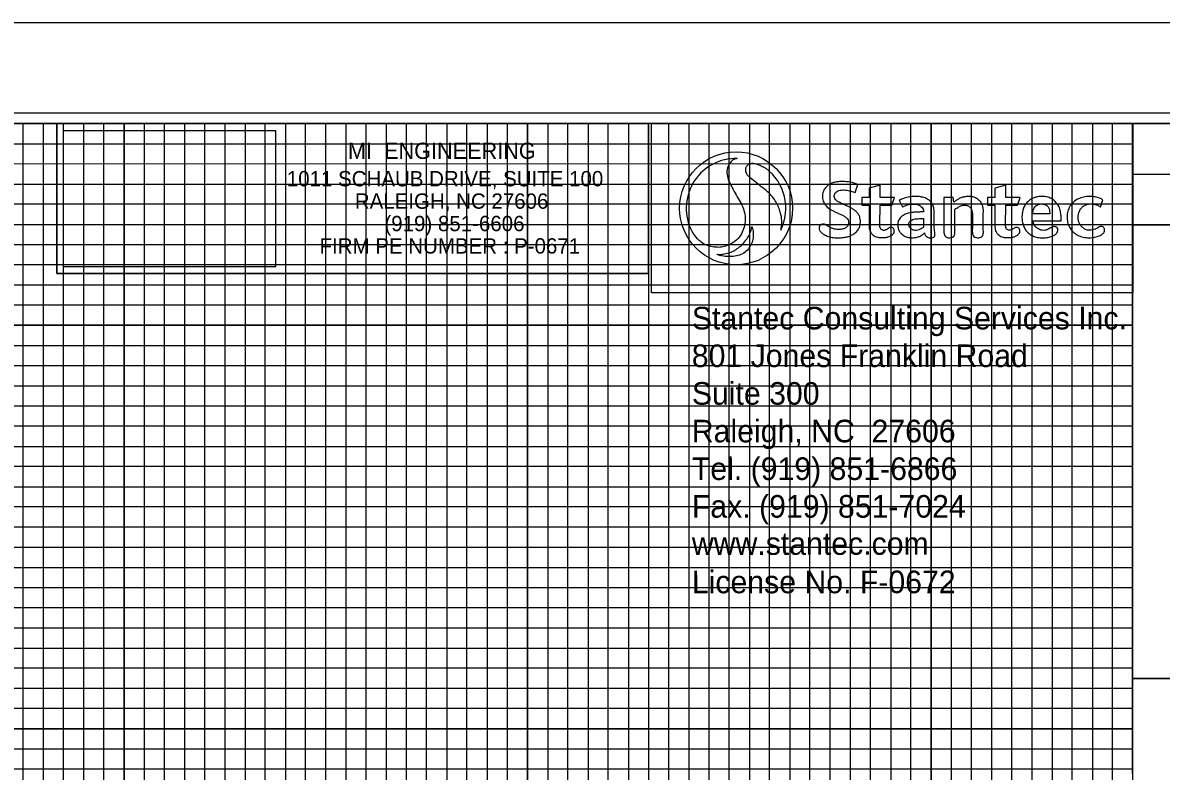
# Model space of a CAD drawing. Extents: x 2331575 to 2333259, y 609001 to 610101.
# Drawn here: x 2332767.1 to 2333049.3, y 609916 to 610101.5 of the extents above; entities that cross this region are included whole.
import ezdxf

# ---------------------------------------------------------------- set-up
doc = ezdxf.new("R2010")
doc.units = 0
for name, color, linetype in [('Old_Level_1', 7, 'Continuous'), ('Prop DSN Text', 7, 'Continuous'), ('Prop Grid Mask', 7, 'Continuous'), ('Scratch_Level_0', 7, 'Continuous'), ('Sheet Cutting Line CELL', 7, 'Continuous'), ('Sheet Data Text CELL', 7, 'Continuous'), ('Sheet DOT Grid CELL', 7, 'Continuous'), ('Sheet Plot Border Inside CELL', 7, 'Continuous'), ('Sheet Plot Border Outside CELL', 7, 'Continuous'), ('Sheet Profile CELL', 7, 'Continuous'), ('Sheet Profile Grid Major CELL', 7, 'Continuous'), ('Sheet Profile Grid Middle CELL', 7, 'Continuous'), ('Sheet Profile Grid Minor CELL', 7, 'Continuous'), ('Sheet Sticker Exception Certification CELL', 7, 'Continuous')]:
    doc.layers.add(name, color=color, linetype=linetype)

msp = doc.modelspace()

# ---------------------------------------------------------------- linework, layer by layer
at = {"layer": 'Old_Level_1'}
msp.add_lwpolyline([(2332775.56, 610076.48), (2332922.23, 610076.48), (2332922.23, 610039.3), (2332775.56, 610039.3)], close=True, dxfattribs=at)
at = {"layer": 'Prop DSN Text'}
msp.add_lwpolyline([(2332777.18, 610041.08), (2332829.85, 610041.08), (2332829.85, 610074.7), (2332777.18, 610074.7)], close=True, dxfattribs=at)
at = {"layer": 'Prop Grid Mask'}
for points in [[(2332922.23, 610076.48), (2332775.56, 610076.48), (2332775.56, 610039.3), (2332922.23, 610039.3)], [(2333042.23, 610076.48), (2332922.23, 610076.48), (2332922.23, 609951.48), (2333042.23, 609951.48)]]:
    msp.add_lwpolyline(points, close=True, dxfattribs=at)
at = {"layer": 'Scratch_Level_0'}
msp.add_lwpolyline([(2332922.93, 610076.46), (2333042.23, 610076.48), (2333042.23, 610034.52), (2332922.94, 610034.51)], close=True, dxfattribs=at)
at = {"layer": 'Sheet Cutting Line CELL'}
msp.add_line((2333259.23, 610101.48), (2331575.23, 610101.48), dxfattribs=at)
at = {"layer": 'Sheet Data Text CELL'}
for p, q in [((2332973.44, 610059.4), (2332974.12, 610061.35)), ((2332979.62, 610061.24), (2332976.87, 610060.47)), ((2332976.87, 610060.47), (2332976.87, 610058.18)), ((2332979.62, 610058.18), (2332979.62, 610061.24)), ((2333010.77, 610061.24), (2333008.02, 610060.47)), ((2333008.02, 610060.47), (2333008.02, 610058.18)), ((2333010.77, 610058.18), (2333010.77, 610061.24)), ((2332976.87, 610058.18), (2332975.11, 610058.18)), ((2332975.11, 610058.18), (2332975.11, 610056.26)), ((2332983.19, 610058.18), (2332979.62, 610058.18)), ((2332982.52, 610056.26), (2332983.19, 610058.18)), ((2332984.34, 610057.48), (2332985.18, 610055.85)), ((2332997.75, 610058.17), (2332995.43, 610058.17)), ((2332995.43, 610058.17), (2332995.43, 610049.38)), ((2332997.9, 610057.01), (2332997.75, 610058.17)), ((2333008.02, 610058.18), (2333006.26, 610058.18)), ((2333006.26, 610058.18), (2333006.26, 610056.26)), ((2333014.34, 610058.18), (2333010.77, 610058.18)), ((2333013.67, 610056.26), (2333014.34, 610058.18)), ((2333034.23, 610055.8), (2333034.84, 610057.6)), ((2332975.11, 610056.26), (2332976.89, 610056.26)), ((2332979.57, 610051.41), (2332979.61, 610056.26)), ((2332979.61, 610056.26), (2332982.52, 610056.26)), ((2332998.13, 610049.38), (2332998.13, 610055.18)), ((2333006.26, 610056.26), (2333008.04, 610056.26)), ((2333010.72, 610051.42), (2333010.76, 610056.26)), ((2333010.76, 610056.26), (2333013.67, 610056.26)), ((2333021.68, 610054.08), (2333017.47, 610054.08)), ((2332990.36, 610052.97), (2332990.36, 610050.79)), ((2333017.47, 610052.39), (2333024.47, 610052.39))]:
    msp.add_line(p, q, dxfattribs=at)
for points in [[(2332944.18, 610067.83), (2332944.18, 610067.83)], [(2332951.27, 610065.41), (2332951.27, 610065.4)]]:
    msp.add_lwpolyline(points, dxfattribs=at)
msp.add_circle((2332943.91, 610055.49), 14, dxfattribs=at)
for start, end in [(88.7738, 203.6916), (88.7673, 88.7738), (333.7886, 53.4398), (247.1256, 251.4651)]:
    msp.add_arc((2332943.91, 610055.49), 12.34, start, end, dxfattribs=at)
for points, degree in [([(2332944.18, 610067.83), (2332943.88, 610067.77), (2332943.18, 610067.62), (2332942.26, 610066.68), (2332941.58, 610065.15), (2332941.67, 610063.42), (2332942.28, 610061.76), (2332943.2, 610060.14), (2332944.15, 610058.35), (2332945.21, 610056.66), (2332945.94, 610054.95), (2332946.29, 610053.09), (2332946.06, 610051.22), (2332945.52, 610049.51), (2332944.47, 610047.95), (2332943.08, 610046.85), (2332941.64, 610046.2), (2332940.33, 610045.8), (2332938.87, 610045.8), (2332937.24, 610046.02), (2332935.64, 610046.76), (2332933.93, 610048.2), (2332933.11, 610049.62), (2332932.61, 610050.53)], 3), ([(2332944.18, 610067.83), (2332944.18, 610067.83), (2332944.18, 610067.83), (2332944.18, 610067.83)], 2), ([(2332954.99, 610050.04), (2332955.09, 610050.47), (2332955.28, 610051.28), (2332955.24, 610052.59), (2332955.12, 610053.73), (2332954.78, 610054.8), (2332954.38, 610056.03), (2332953.69, 610057.36), (2332952.69, 610058.62), (2332951.39, 610059.95), (2332949.77, 610061.13), (2332948.1, 610062.49), (2332946.76, 610063.5), (2332946.28, 610064.68), (2332946.28, 610065.58), (2332946.72, 610066.19), (2332947.32, 610066.62), (2332948.11, 610066.69), (2332949.04, 610066.51), (2332950.12, 610066.05), (2332950.86, 610065.63), (2332951.27, 610065.41)], 3), ([(2332974.12, 610061.35), (2332974, 610061.41), (2332973.46, 610061.67), (2332972.42, 610061.95), (2332971.14, 610062.1), (2332969.99, 610062.16), (2332969.02, 610062.07), (2332968.09, 610061.88), (2332967.2, 610061.52), (2332966.34, 610060.93), (2332965.73, 610060.14), (2332965.38, 610059.35), (2332965.3, 610058.6), (2332965.33, 610057.92), (2332965.48, 610057.27), (2332965.76, 610056.72), (2332966.09, 610056.23), (2332966.51, 610055.79), (2332967.01, 610055.39), (2332967.63, 610055.02), (2332968.4, 610054.62), (2332969.25, 610054.23), (2332970.11, 610053.86), (2332970.83, 610053.5), (2332971.35, 610053.05), (2332971.71, 610052.63), (2332971.84, 610052.12), (2332971.82, 610051.63), (2332971.62, 610051.09), (2332971.18, 610050.65), (2332970.47, 610050.34), (2332969.63, 610050.22), (2332968.7, 610050.26), (2332967.87, 610050.43), (2332967.21, 610050.76), (2332966.67, 610050.98), (2332966.31, 610051.32), (2332965.96, 610051.45), (2332965.65, 610051.59), (2332965.31, 610051.57), (2332964.97, 610051.46), (2332964.68, 610051.21), (2332964.49, 610050.86), (2332964.48, 610050.46), (2332964.53, 610050.08), (2332964.84, 610049.67), (2332965.42, 610049.08), (2332966.46, 610048.57), (2332967.75, 610048.23), (2332969.05, 610048.16), (2332970.17, 610048.2), (2332971.15, 610048.32), (2332972.01, 610048.58), (2332972.9, 610048.99), (2332973.76, 610049.66), (2332974.43, 610050.5), (2332974.71, 610051.49), (2332974.75, 610052.38), (2332974.64, 610053.19), (2332974.32, 610053.84), (2332973.94, 610054.49), (2332973.27, 610055.03), (2332972.51, 610055.54), (2332971.67, 610055.95), (2332970.76, 610056.37), (2332969.82, 610056.78), (2332969.02, 610057.2), (2332968.48, 610057.69), (2332968.25, 610058.16), (2332968.21, 610058.66), (2332968.35, 610059.12), (2332968.66, 610059.51), (2332969.09, 610059.8), (2332969.66, 610060), (2332970.34, 610060.05), (2332971.01, 610060.03), (2332971.67, 610059.92), (2332972.31, 610059.79), (2332972.91, 610059.6), (2332973.28, 610059.46), (2332973.44, 610059.4)], 3), ([(2332990.63, 610049.43), (2332990.64, 610049.34), (2332990.66, 610049.11), (2332990.88, 610048.77), (2332991.21, 610048.4), (2332991.79, 610048.12), (2332992.41, 610048.14), (2332992.99, 610048.27), (2332993.21, 610048.72), (2332993.22, 610049.18), (2332993.09, 610049.79), (2332992.95, 610051.48), (2332993.06, 610053.26), (2332993.03, 610055.19), (2332992.8, 610056.12), (2332992.28, 610056.96), (2332991.71, 610057.6), (2332990.78, 610058.08), (2332989.63, 610058.38), (2332988.26, 610058.46), (2332986.88, 610058.33), (2332985.55, 610058.02), (2332984.73, 610057.65), (2332984.34, 610057.48)], 3), ([(2332985.18, 610055.85), (2332985.3, 610055.92), (2332985.69, 610056.12), (2332986.31, 610056.32), (2332987.06, 610056.51), (2332987.78, 610056.56), (2332988.52, 610056.53), (2332989.19, 610056.32), (2332989.77, 610055.99), (2332990.18, 610055.5), (2332990.36, 610055), (2332990.36, 610054.69), (2332990.36, 610054.59)], 3), ([(2332998.13, 610055.18), (2332998.18, 610055.22), (2332998.37, 610055.4), (2332998.82, 610055.67), (2332999.4, 610056.06), (2333000.14, 610056.29), (2333000.9, 610056.28), (2333001.63, 610056.04), (2333002.13, 610055.52), (2333002.4, 610054.91), (2333002.54, 610054.07), (2333002.45, 610052.82), (2333002.51, 610051.23), (2333002.43, 610049.91), (2333002.49, 610048.99), (2333002.8, 610048.5), (2333003.35, 610048.15), (2333003.99, 610048.16), (2333004.6, 610048.31), (2333005.09, 610048.69), (2333005.24, 610049.41), (2333005.13, 610050.69), (2333005.2, 610052.26), (2333005.16, 610053.99), (2333005.23, 610055.09), (2333005.08, 610056.04), (2333004.78, 610056.71), (2333004.3, 610057.4), (2333003.54, 610057.94), (2333002.57, 610058.39), (2333001.47, 610058.42), (2333000.48, 610058.37), (2332999.6, 610058.07), (2332998.8, 610057.7), (2332998.28, 610057.29), (2332998, 610057.07), (2332997.9, 610057.01)], 3), ([(2333024.47, 610052.39), (2333024.48, 610052.66), (2333024.5, 610053.33), (2333024.38, 610054.41), (2333024.11, 610055.62), (2333023.53, 610056.55), (2333022.87, 610057.36), (2333022.04, 610057.93), (2333020.98, 610058.35), (2333019.8, 610058.42), (2333018.63, 610058.4), (2333017.53, 610058.05), (2333016.58, 610057.51), (2333015.76, 610056.73), (2333015.2, 610055.78), (2333014.89, 610054.74), (2333014.77, 610053.68), (2333014.75, 610052.53), (2333015, 610051.47), (2333015.42, 610050.44), (2333016.06, 610049.55), (2333017.04, 610048.85), (2333018.25, 610048.25), (2333019.66, 610048.18), (2333020.94, 610048.19), (2333022.03, 610048.43), (2333022.89, 610048.84), (2333023.51, 610049.38), (2333023.74, 610049.97), (2333023.64, 610050.45), (2333023.4, 610050.83), (2333023.03, 610050.94), (2333022.65, 610050.99), (2333022.23, 610050.85), (2333021.72, 610050.53), (2333021.13, 610050.18), (2333020.42, 610050.02), (2333019.76, 610050), (2333019.11, 610050.17), (2333018.57, 610050.54), (2333018.04, 610050.98), (2333017.72, 610051.56), (2333017.53, 610052.04), (2333017.49, 610052.3), (2333017.47, 610052.39)], 3), ([(2333017.47, 610054.08), (2333017.47, 610054.17), (2333017.47, 610054.38), (2333017.5, 610054.79), (2333017.64, 610055.32), (2333017.96, 610055.87), (2333018.47, 610056.32), (2333019.17, 610056.57), (2333019.92, 610056.59), (2333020.61, 610056.38), (2333021.2, 610055.99), (2333021.5, 610055.35), (2333021.64, 610054.7), (2333021.67, 610054.27), (2333021.68, 610054.08)], 3), ([(2333034.84, 610057.6), (2333034.61, 610057.73), (2333034.03, 610058.05), (2333032.91, 610058.34), (2333031.52, 610058.49), (2333030.04, 610058.32), (2333028.62, 610057.85), (2333027.45, 610057.07), (2333026.61, 610056.01), (2333026.08, 610054.79), (2333025.9, 610053.41), (2333026.01, 610052.03), (2333026.48, 610050.78), (2333027.18, 610049.83), (2333028.16, 610049), (2333029.49, 610048.37), (2333031.06, 610048.13), (2333032.5, 610048.22), (2333033.68, 610048.53), (2333034.62, 610048.97), (2333035.23, 610049.56), (2333035.27, 610050.12), (2333035.22, 610050.54), (2333034.93, 610050.79), (2333034.65, 610050.97), (2333034.33, 610050.99), (2333033.89, 610050.92), (2333033.51, 610050.58), (2333032.95, 610050.35), (2333032.39, 610050.09), (2333031.6, 610050.02), (2333030.76, 610050.1), (2333029.96, 610050.53), (2333029.36, 610051.14), (2333028.87, 610051.87), (2333028.73, 610052.72), (2333028.6, 610053.57), (2333028.85, 610054.41), (2333029.17, 610055.18), (2333029.65, 610055.79), (2333030.29, 610056.25), (2333031.02, 610056.53), (2333031.88, 610056.61), (2333032.74, 610056.52), (2333033.57, 610056.26), (2333034.01, 610055.95), (2333034.23, 610055.8)], 3), ([(2332976.89, 610056.26), (2332976.88, 610054.54), (2332976.87, 610052.74), (2332976.89, 610050.72), (2332976.98, 610050.24), (2332977.17, 610049.58), (2332977.54, 610049.13), (2332977.92, 610048.78), (2332978.33, 610048.51), (2332978.97, 610048.29), (2332979.85, 610048.19), (2332980.76, 610048.23), (2332981.67, 610048.36), (2332982.36, 610048.71), (2332982.87, 610049.12), (2332983.11, 610049.59), (2332983.13, 610050.01), (2332983.05, 610050.35), (2332982.87, 610050.56), (2332982.65, 610050.69), (2332982.39, 610050.74), (2332982.12, 610050.74), (2332981.85, 610050.67), (2332981.6, 610050.47), (2332981.32, 610050.26), (2332980.98, 610050.11), (2332980.62, 610050), (2332980.25, 610050.04), (2332979.92, 610050.22), (2332979.67, 610050.47), (2332979.56, 610050.9), (2332979.57, 610051.21), (2332979.57, 610051.41)], 3), ([(2332990.36, 610054.59), (2332990.18, 610054.59), (2332989.6, 610054.58), (2332988.6, 610054.53), (2332987.41, 610054.47), (2332986.3, 610054.22), (2332985.27, 610053.8), (2332984.38, 610053.02), (2332983.96, 610051.94), (2332984.02, 610050.91), (2332984.18, 610050.03), (2332984.72, 610049.29), (2332985.5, 610048.61), (2332986.6, 610048.19), (2332987.76, 610048.17), (2332988.82, 610048.31), (2332989.63, 610048.6), (2332990.24, 610049.01), (2332990.49, 610049.28), (2332990.63, 610049.43)], 3), ([(2333008.04, 610056.26), (2333008.03, 610054.55), (2333008.02, 610052.74), (2333008.04, 610050.72), (2333008.13, 610050.24), (2333008.32, 610049.58), (2333008.69, 610049.13), (2333009.08, 610048.78), (2333009.48, 610048.52), (2333010.12, 610048.29), (2333011, 610048.2), (2333011.91, 610048.23), (2333012.82, 610048.36), (2333013.51, 610048.71), (2333014.02, 610049.12), (2333014.26, 610049.6), (2333014.28, 610050.01), (2333014.2, 610050.36), (2333014.02, 610050.56), (2333013.8, 610050.69), (2333013.54, 610050.74), (2333013.27, 610050.74), (2333013, 610050.67), (2333012.75, 610050.48), (2333012.47, 610050.27), (2333012.13, 610050.12), (2333011.77, 610050), (2333011.4, 610050.05), (2333011.07, 610050.22), (2333010.82, 610050.47), (2333010.71, 610050.91), (2333010.72, 610051.22), (2333010.72, 610051.42)], 3), ([(2332939.11, 610044.11), (2332939.42, 610044.08), (2332940.13, 610044.01), (2332941.36, 610044.25), (2332942.72, 610044.57), (2332943.95, 610045.29), (2332945.08, 610046.08), (2332946.15, 610047.22), (2332947.03, 610048.5), (2332947.59, 610049.82), (2332947.76, 610050.6), (2332947.84, 610050.97)], 3), ([(2332947.84, 610050.97), (2332947.93, 610050.66), (2332948.16, 610049.85), (2332948.22, 610048.51), (2332947.99, 610047.06), (2332947.24, 610045.74), (2332946.23, 610044.52), (2332944.76, 610043.86), (2332943.21, 610043.5), (2332941.61, 610043.48), (2332940.51, 610043.68), (2332939.99, 610043.78)], 3), ([(2332990.36, 610050.79), (2332990.29, 610050.74), (2332990.04, 610050.54), (2332989.57, 610050.29), (2332988.92, 610050.02), (2332988.22, 610049.98), (2332987.62, 610050.14), (2332987.2, 610050.41), (2332986.93, 610050.73), (2332986.75, 610051.11), (2332986.72, 610051.53), (2332986.8, 610051.94), (2332987.04, 610052.33), (2332987.47, 610052.59), (2332987.97, 610052.81), (2332988.64, 610052.9), (2332989.32, 610052.94), (2332989.92, 610052.98), (2332990.23, 610052.97), (2332990.36, 610052.97)], 3), ([(2332995.43, 610049.38), (2332995.46, 610049.26), (2332995.51, 610049.01), (2332995.71, 610048.56), (2332996.2, 610048.18), (2332996.89, 610048.18), (2332997.58, 610048.23), (2332997.99, 610048.68), (2332998.13, 610049.07), (2332998.13, 610049.29), (2332998.13, 610049.38)], 3)]:
    msp.add_open_spline(points, degree=degree, dxfattribs=at)
at = {"layer": 'Sheet DOT Grid CELL'}
for p, q in [((2332792.23, 609576.48), (2332792.23, 610076.48)), ((2332842.23, 609576.48), (2332842.23, 610076.48)), ((2332892.23, 609576.48), (2332892.23, 610076.48)), ((2332942.23, 609576.48), (2332942.23, 610076.48)), ((2332992.23, 609576.48), (2332992.23, 610076.48)), ((2333042.18, 610026.48), (2331742.23, 610026.48)), ((2333042.18, 609976.48), (2331742.23, 609976.48)), ((2333042.23, 609576.48), (2333042.23, 609938.93)), ((2333042.23, 609926.48), (2331742.23, 609926.48))]:
    msp.add_line(p, q, dxfattribs=at)
at = {"layer": 'Sheet Plot Border Inside CELL'}
msp.add_lwpolyline([(2331588.23, 609023.93), (2333254.73, 609023.93), (2333254.73, 610079.03), (2331588.23, 610079.03)], close=True, dxfattribs=at)
at = {"layer": 'Sheet Plot Border Outside CELL'}
msp.add_lwpolyline([(2331575.23, 609001.48), (2333259.23, 609001.48), (2333259.23, 610101.48), (2331575.23, 610101.48)], close=True, dxfattribs=at)
at = {"layer": 'Sheet Profile CELL'}
msp.add_line((2333042.18, 610063.93), (2333242.23, 610063.93), dxfattribs=at)
for points in [[(2333242.23, 610076.48), (2331742.23, 610076.48), (2331742.23, 609026.48), (2333242.23, 609026.48)], [(2333042.18, 610076.48), (2333242.23, 610076.48), (2333242.23, 610051.43), (2333042.18, 610051.43)], [(2333042.18, 610051.43), (2333142.23, 610051.43), (2333142.23, 609938.93), (2333042.18, 609938.93)]]:
    msp.add_lwpolyline(points, close=True, dxfattribs=at)
at = {"layer": 'Sheet Profile Grid Major CELL'}
for points in [[(2332742.23, 610076.48), (2332792.23, 610076.48), (2332792.23, 609576.48), (2332842.23, 609576.48), (2332842.23, 610076.48), (2332892.23, 610076.48), (2332892.23, 609576.48), (2332942.23, 609576.48), (2332942.23, 610076.48), (2332992.23, 610076.48), (2332992.23, 609576.48), (2333042.23, 609576.48), (2333042.23, 610076.48), (2333068.53, 610076.48)], [(2331742.23, 610026.48), (2333042.23, 610026.48)], [(2333042.23, 609976.48), (2331742.23, 609976.48), (2331742.23, 609926.48), (2333042.23, 609926.48)]]:
    msp.add_lwpolyline(points, dxfattribs=at)
at = {"layer": 'Sheet Profile Grid Middle CELL'}
msp.add_line((2331742.23, 610051.48), (2333042.18, 610051.48), dxfattribs=at)
for points in [[(2332717.23, 609576.48), (2332767.23, 609576.48), (2332767.23, 610076.48), (2332817.23, 610076.48), (2332817.23, 609576.48), (2332867.23, 609576.48), (2332867.23, 610076.48), (2332917.23, 610076.48), (2332917.23, 609576.48), (2332967.23, 609576.48), (2332967.23, 610076.48), (2333017.23, 610076.48), (2333017.23, 609576.48), (2333067.23, 609576.48), (2333067.23, 609915.43)], [(2333042.23, 610001.48), (2331742.23, 610001.48), (2331742.23, 609951.48), (2333042.23, 609951.48)]]:
    msp.add_lwpolyline(points, dxfattribs=at)
at = {"layer": 'Sheet Profile Grid Minor CELL'}
for p, q in [((2331792.23, 610071.48), (2333042.23, 610071.48)), ((2333042.23, 610066.48), (2331792.23, 610066.13)), ((2331792.23, 610061.48), (2333042.23, 610061.48)), ((2333042.18, 609941.48), (2331792.23, 609941.48)), ((2333042.23, 609936.48), (2331792.23, 609936.48)), ((2333042.23, 609931.48), (2331792.23, 609931.48)), ((2331792.23, 609921.48), (2333042.23, 609921.48)), ((2333042.23, 609916.48), (2331792.23, 609916.48))]:
    msp.add_line(p, q, dxfattribs=at)
for points in [[(2332762.23, 610076.48), (2332772.23, 610076.48), (2332772.23, 609576.48)], [(2332777.23, 609576.48), (2332777.23, 610076.48), (2332782.23, 610076.48), (2332782.23, 609576.48)], [(2332787.23, 609576.48), (2332787.23, 610076.48), (2332797.23, 610076.48), (2332797.23, 609576.48)], [(2332802.23, 609576.48), (2332802.23, 610076.48), (2332807.23, 610076.48), (2332807.23, 609576.48)], [(2332812.23, 609576.48), (2332812.23, 610076.48), (2332822.23, 610076.48), (2332822.23, 609576.48)], [(2332827.23, 609576.48), (2332827.23, 610076.48), (2332832.23, 610076.48), (2332832.23, 609576.48)], [(2332837.23, 609576.48), (2332837.23, 610076.48), (2332847.23, 610076.48), (2332847.23, 609576.48)], [(2332852.23, 609576.48), (2332852.23, 610076.48), (2332857.23, 610076.48), (2332857.23, 609576.48)], [(2332862.23, 609576.48), (2332862.23, 610076.48), (2332872.23, 610076.48), (2332872.23, 609576.48)], [(2332877.23, 609576.48), (2332877.23, 610076.48), (2332882.23, 610076.48), (2332882.23, 609576.48)], [(2332887.23, 609576.48), (2332887.23, 610076.48), (2332897.23, 610076.48), (2332897.23, 609576.48)], [(2332902.23, 609576.48), (2332902.23, 610076.48), (2332907.23, 610076.48), (2332907.23, 609576.48)], [(2332912.23, 609576.48), (2332912.23, 610076.48), (2332922.23, 610076.48), (2332922.23, 609576.48)], [(2332927.23, 609576.48), (2332927.23, 610076.48), (2332932.23, 610076.48), (2332932.23, 609576.48)], [(2332937.23, 609576.48), (2332937.23, 610076.48), (2332947.23, 610076.48), (2332947.23, 609576.48)], [(2332952.23, 609576.48), (2332952.23, 610076.48), (2332957.23, 610076.48), (2332957.23, 609576.48)], [(2332962.23, 609576.48), (2332962.23, 610076.48), (2332972.23, 610076.48), (2332972.23, 609576.48)], [(2332977.23, 609576.48), (2332977.23, 610076.48), (2332982.23, 610076.48), (2332982.23, 609576.48)], [(2332987.23, 609576.48), (2332987.23, 610076.48), (2332997.23, 610076.48), (2332997.23, 609576.48)], [(2333002.23, 609576.48), (2333002.23, 610076.48), (2333007.23, 610076.48), (2333007.23, 609576.48)], [(2333012.23, 609576.48), (2333012.23, 610076.48), (2333022.23, 610076.48), (2333022.23, 609576.48)], [(2333027.23, 609576.48), (2333027.23, 610076.48), (2333032.23, 610076.48), (2333032.23, 609576.48)], [(2333037.23, 609576.48), (2333037.23, 610076.48), (2333047.23, 610076.48)], [(2333042.23, 610056.48), (2331792.23, 610056.48), (2331792.23, 610046.48), (2333042.23, 610046.48)], [(2333042.18, 610041.48), (2331792.23, 610041.48), (2331792.23, 610036.48), (2333042.23, 610036.48)], [(2333042.23, 610031.48), (2331792.23, 610031.48), (2331792.23, 610021.48), (2333042.23, 610021.48)], [(2333042.23, 610016.48), (2331792.23, 610016.48), (2331792.23, 610011.48), (2333042.23, 610011.48)], [(2333042.23, 610006.48), (2331792.23, 610006.48), (2331792.23, 609996.48), (2333042.23, 609996.48)], [(2333042.23, 609991.48), (2331792.23, 609991.48), (2331792.23, 609986.48), (2333042.23, 609986.48)], [(2333042.23, 609981.48), (2331792.23, 609981.48), (2331792.23, 609971.48), (2333042.23, 609971.48)], [(2333042.23, 609966.38), (2331792.33, 609966.38), (2331792.33, 609961.48), (2333042.23, 609961.48)], [(2333042.23, 609956.48), (2331792.23, 609956.48), (2331792.23, 609946.48), (2333042.23, 609946.48)]]:
    msp.add_lwpolyline(points, dxfattribs=at)
at = {"layer": 'Sheet Sticker Exception Certification CELL'}
for p, q in [((2333042.18, 609915.43), (2333042.18, 609938.93)), ((2333042.18, 609938.93), (2333242.21, 609938.93)), ((2333042.18, 609915.43), (2333042.18, 609938.93)), ((2333042.18, 609938.93), (2333242.21, 609938.93))]:
    msp.add_line(p, q, dxfattribs=at)

# ---------------------------------------------------------------- texts
at = {"layer": 'Prop Grid Mask'}
for s, height, rotation, p in [('MI  ENGINEERING', 4.0137, 360, (2332847.73, 610067.74)), ('1011 SCHAUB DRIVE, SUITE 100', 3.7957, 359.9996, (2332832.58, 610060.93)), ('RALEIGH, NC 27606', 3.7957, 359.9998, (2332849.44, 610055.38)), ('(919) 851-6606', 3.7957, 359.9998, (2332856.77, 610049.82)), ('FIRM PE NUMBER : P-0671', 3.7957, 359.9998, (2332840.68, 610044.27))]:
    msp.add_text(s, height=height, rotation=rotation, dxfattribs=at).set_placement(p)
at = {"layer": 'Sheet Data Text CELL'}
for s, height, p in [('Stantec Consulting Services Inc.', 5.6014, (2332932.95, 610025.46)), ('801 Jones Franklin Road', 5.6014, (2332932.95, 610016.13)), ('Suite 300', 5.601, (2332932.95, 610006.8)), ('Raleigh, NC  27606', 5.6014, (2332932.95, 609997.47)), ('Tel. (919) 851-6866', 5.6014, (2332932.96, 609988.14)), ('Fax. (919) 851-7024', 5.6014, (2332932.96, 609978.8)), ('www.stantec.com', 5.6014, (2332932.96, 609969.59)), ('License No. F-0672', 5.6014, (2332932.96, 609960.07))]:
    msp.add_text(s, height=height, rotation=0.0071, dxfattribs=at).set_placement(p)

doc.saveas('drawing.dxf')
